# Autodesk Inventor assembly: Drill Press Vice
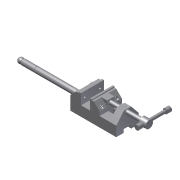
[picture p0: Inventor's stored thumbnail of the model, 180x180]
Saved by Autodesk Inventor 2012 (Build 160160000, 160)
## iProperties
Created: 2009-05
Part Number: Drill Press Vice
Document SubType Name: Assembly
Designer: Sham
Author: Sham
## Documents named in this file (9)
- C:\Users\CadCim\Documents\SAILESH\inventor-2011-fact-prt\c1211inv_2012-prt\c12_inv_2012_prt\Tutorials\c12_tut03_inv\Drill Press Vice.iam
- C:\Users\CadCim\Documents\SAILESH\inventor-2011-fact-prt\c1211inv_2012-prt\c12_inv_2012_prt\Tutorials\c12_tut03_inv\Base.ipt
- C:\Users\CadCim\Documents\SAILESH\inventor-2011-fact-prt\c1211inv_2012-prt\c12_inv_2012_prt\Tutorials\c12_tut03_inv\Safety Handle.ipt
- C:\Users\CadCim\Documents\SAILESH\inventor-2011-fact-prt\c1211inv_2012-prt\c12_inv_2012_prt\Tutorials\c12_tut03_inv\Jaw Face.ipt
- C:\Users\CadCim\Documents\SAILESH\inventor-2011-fact-prt\c1211inv_2012-prt\c12_inv_2012_prt\Tutorials\c12_tut03_inv\Movable Jaw.ipt
- C:\Users\CadCim\Documents\SAILESH\inventor-2011-fact-prt\c1211inv_2012-prt\c12_inv_2012_prt\Tutorials\c12_tut03_inv\Cap Screw.ipt
- C:\Users\CadCim\Documents\SAILESH\inventor-2011-fact-prt\c1211inv_2012-prt\c12_inv_2012_prt\Tutorials\c12_tut03_inv\Clamp Screw Handle.ipt
- C:\Users\CadCim\Documents\SAILESH\inventor-2011-fact-prt\c1211inv_2012-prt\c12_inv_2012_prt\Tutorials\c12_tut03_inv\Clamp Screw.ipt
- C:\Users\CadCim\Documents\SAILESH\inventor-2011-fact-prt\c1211inv_2012-prt\c12_inv_2012_prt\Tutorials\c12_tut03_inv\Handle Stop.ipt
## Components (13 placed, 8 different names)
1. Base:1 — Mate:2, Mate:3, Mate:7, Insert:10, Insert:11, Insert:12, Insert:13
2. Safety Handle:1
3. Jaw Face:1 — Insert:8, Insert:9, Mate:7
4. Jaw Face:2 — Insert:10, Insert:11
5. Movable Jaw:1 — Mate:2, Mate:3, Insert:2, Insert:3, Insert:4, Insert:8, Insert:9
6. Cap Screw:1 — Insert:2
7. Cap Screw:2 — Insert:3
8. Cap Screw:3 — Insert:13
9. Cap Screw:4 — Insert:12
10. Clamp Screw:1 — Insert:4, Mate:6, Rotation/Translation:2
11. Clamp Screw Handle:1 — Mate:6, Insert:5, Insert:6, Rotation/Translation:2
12. Handle Stop:1 — Insert:6, Mate:8
13. Handle Stop:2 — Insert:5
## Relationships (17: Insert 11, Mate 5, RelateRotateTranslate 1)
- Mate:2: Base:1 ↔ Movable Jaw:1
- Mate:3: Base:1 ↔ Movable Jaw:1
- Insert:2: Movable Jaw:1 ↔ Cap Screw:1
- Insert:3: Movable Jaw:1 ↔ Cap Screw:2
- Insert:4: Movable Jaw:1 ↔ Clamp Screw:1
- Mate:6: Clamp Screw:1 ↔ Clamp Screw Handle:1
- Insert:5: Clamp Screw Handle:1 ↔ Handle Stop:2
- Insert:6: Clamp Screw Handle:1 ↔ Handle Stop:1
- Insert:8: Jaw Face:1 ↔ Movable Jaw:1
- Insert:9: Jaw Face:1 ↔ Movable Jaw:1
- Mate:7: Base:1 ↔ Jaw Face:1
- Rotation/Translation:2 [RelateRotateTranslate]: Clamp Screw:1 ↔ Clamp Screw Handle:1
- Mate:8: Handle Stop:1
- Insert:10: Base:1 ↔ Jaw Face:2
- Insert:11: Base:1 ↔ Jaw Face:2
- Insert:12: Base:1 ↔ Cap Screw:4
- Insert:13: Base:1 ↔ Cap Screw:3
